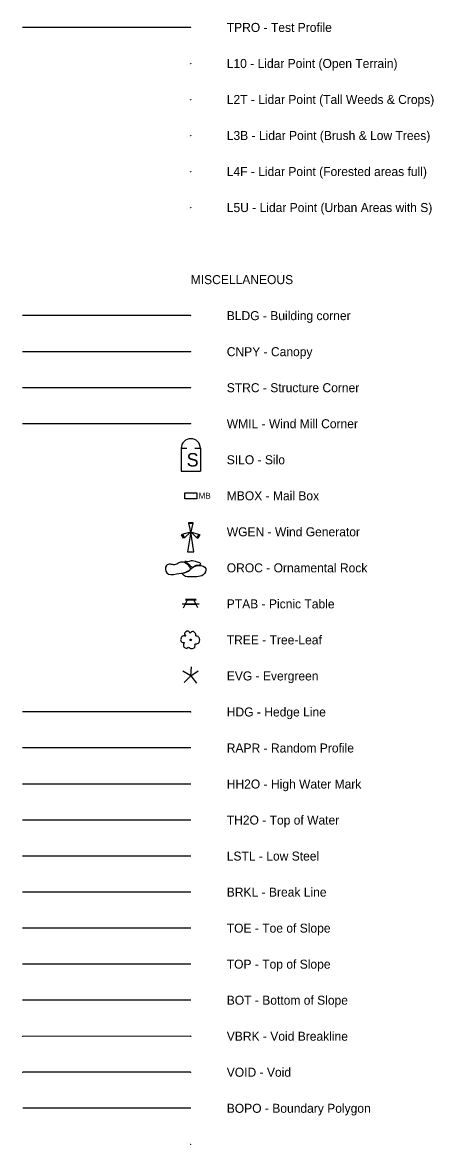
# Model space of a CAD drawing. Extents: x 2147712 to 2176316, y 2125036 to 2131746.
# Drawn here: x 2175974 to 2176316, y 2127274 to 2128208 of the extents above; entities that cross this region are included whole.
import ezdxf

# ---------------------------------------------------------------- set-up
doc = ezdxf.new("R2010")
doc.units = 0
for name, color, linetype in [('BLDG INP', 7, 'Continuous'), ('BRKLN', 7, 'Continuous'), ('Default', 7, 'Continuous'), ('HYD INP', 7, 'Continuous'), ('MANMD STRU INP', 7, 'Continuous'), ('PHO CTRL', 7, 'Continuous'), ('SPOT', 7, 'Continuous'), ('VEG INP', 7, 'Continuous'), ('VOID', 7, 'Continuous')]:
    doc.layers.add(name, color=color, linetype=linetype)

msp = doc.modelspace()

# ---------------------------------------------------------------- linework, layer by layer
at = {"layer": 'BLDG INP'}
for p, q in [((2176114.25, 2127963.72), (2175974.25, 2127963.72)), ((2176114.15, 2127963.52), (2176114.35, 2127963.92)), ((2176114.15, 2127963.92), (2176114.35, 2127963.52))]:
    msp.add_line(p, q, dxfattribs=at)
at = {"layer": 'BRKLN'}
for p, q in [((2176114.25, 2127603.72), (2175974.25, 2127603.72)), ((2176114.25, 2127483.72), (2175974.25, 2127483.72)), ((2176114.25, 2127453.72), (2175974.25, 2127453.72)), ((2176114.25, 2127423.72), (2175974.25, 2127423.72)), ((2176114.25, 2127393.72), (2175974.25, 2127393.72)), ((2176114.25, 2127303.72), (2175974.55, 2127303.72))]:
    msp.add_line(p, q, dxfattribs=at)
at = {"layer": 'Default'}
for p, q in [((2176114.25, 2127573.72), (2175974.25, 2127573.72)), ((2176114.25, 2127513.72), (2175974.25, 2127513.72))]:
    msp.add_line(p, q, dxfattribs=at)
at = {"layer": 'HYD INP'}
msp.add_line((2176114.25, 2127543.72), (2175974.25, 2127543.72), dxfattribs=at)
at = {"layer": 'MANMD STRU INP'}
for p, q in [((2176114.25, 2127933.72), (2175974.25, 2127933.72)), ((2176114.15, 2127933.52), (2176114.35, 2127933.92)), ((2176114.15, 2127933.92), (2176114.35, 2127933.52)), ((2176114.25, 2127903.72), (2175974.25, 2127903.72)), ((2176114.15, 2127903.52), (2176114.35, 2127903.92)), ((2176114.15, 2127903.92), (2176114.35, 2127903.52)), ((2176114.25, 2127873.72), (2175974.25, 2127873.72)), ((2176114.15, 2127873.52), (2176114.35, 2127873.92)), ((2176114.15, 2127873.92), (2176114.35, 2127873.52)), ((2176106.35, 2127853.32), (2176106.35, 2127834.12)), ((2176106.35, 2127853.32), (2176110.95, 2127853.32)), ((2176117.55, 2127853.32), (2176122.35, 2127853.32)), ((2176122.35, 2127853.32), (2176122.35, 2127834.12)), ((2176114.35, 2127843.72), (2176114.35, 2127843.72)), ((2176106.35, 2127834.12), (2176122.35, 2127834.12)), ((2176116.55, 2127815.32), (2176116.55, 2127815.32)), ((2176108.15, 2127720.32), (2176111.75, 2127727.52)), ((2176109.85, 2127727.52), (2176118.65, 2127727.52)), ((2176109.85, 2127727.22), (2176118.65, 2127727.22)), ((2176120.25, 2127720.32), (2176116.65, 2127727.52)), ((2176107.15, 2127723.72), (2176121.25, 2127723.72)), ((2176109.85, 2127723.52), (2176118.65, 2127723.52))]:
    msp.add_line(p, q, dxfattribs=at)
for points in [[(2176109.25, 2127816.32), (2176119.25, 2127816.32), (2176119.25, 2127811.12), (2176109.25, 2127811.12)], [(2176112.65, 2127791.62), (2176116.05, 2127791.62), (2176116.05, 2127790.82), (2176112.65, 2127790.82)], [(2176114.25, 2127783.72), (2176112.65, 2127790.82), (2176116.05, 2127790.82)], [(2176108.25, 2127778.32), (2176106.45, 2127781.32), (2176107.25, 2127781.82), (2176109.05, 2127778.82)], [(2176114.25, 2127783.72), (2176109.05, 2127778.82), (2176107.25, 2127781.82)], [(2176114.25, 2127783.72), (2176111.65, 2127767.02), (2176116.85, 2127767.02)], [(2176114.25, 2127783.72), (2176121.15, 2127781.62), (2176119.45, 2127778.62)], [(2176121.85, 2127781.22), (2176120.25, 2127778.22), (2176119.45, 2127778.62), (2176121.15, 2127781.62)]]:
    msp.add_lwpolyline(points, close=True, dxfattribs=at)
msp.add_arc((2176114.31, 2127853.29), 8, 0, 180, dxfattribs=at)
for points in [[(2176104.35, 2127757.92), (2176100.75, 2127756.32), (2176097.35, 2127756.72), (2176094.05, 2127755.72), (2176094.35, 2127749.52), (2176102.35, 2127748.62), (2176113.95, 2127753.12), (2176109.15, 2127758.12), (2176105.85, 2127758.42), (2176104.25, 2127757.82)], [(2176107.55, 2127749.22), (2176112.85, 2127751.62), (2176115.85, 2127754.02), (2176120.95, 2127755.72), (2176126.75, 2127753.22), (2176124.65, 2127747.92), (2176119.35, 2127746.32), (2176112.35, 2127746.22), (2176108.15, 2127747.62), (2176107.35, 2127749.02)], [(2176109.55, 2127758.62), (2176113.25, 2127756.32), (2176115.15, 2127754.42), (2176115.75, 2127754.32), (2176117.75, 2127755.52), (2176119.75, 2127755.92), (2176121.45, 2127756.22), (2176122.55, 2127757.02), (2176119.75, 2127758.42), (2176114.75, 2127759.52), (2176110.55, 2127758.92), (2176109.35, 2127759.02), (2176109.45, 2127758.72), (2176109.75, 2127758.42)]]:
    msp.add_spline(points, degree=3, dxfattribs=at)
at = {"layer": 'PHO CTRL'}
for p, q in [((2176114.25, 2128203.72), (2175974.25, 2128203.72)), ((2176114.15, 2128203.52), (2176114.35, 2128203.92)), ((2176114.15, 2128203.92), (2176114.35, 2128203.52)), ((2176114.15, 2128173.52), (2176114.35, 2128173.92)), ((2176114.15, 2128173.92), (2176114.35, 2128173.52)), ((2176114.15, 2128143.52), (2176114.35, 2128143.92)), ((2176114.15, 2128143.92), (2176114.35, 2128143.52)), ((2176114.15, 2128113.52), (2176114.35, 2128113.92)), ((2176114.15, 2128113.92), (2176114.35, 2128113.52)), ((2176114.15, 2128083.52), (2176114.35, 2128083.92)), ((2176114.15, 2128083.92), (2176114.35, 2128083.52)), ((2176114.15, 2128053.52), (2176114.35, 2128053.92)), ((2176114.15, 2128053.92), (2176114.35, 2128053.52))]:
    msp.add_line(p, q, dxfattribs=at)
at = {"layer": 'SPOT'}
for p, q in [((2176114.15, 2127273.52), (2176114.35, 2127273.92)), ((2176114.15, 2127273.92), (2176114.35, 2127273.52))]:
    msp.add_line(p, q, dxfattribs=at)
at = {"layer": 'VEG INP'}
for p, q in [((2176114.25, 2127663.72), (2176114.85, 2127671.22)), ((2176114.25, 2127663.72), (2176120.55, 2127667.92)), ((2176114.25, 2127663.72), (2176107.65, 2127667.62)), ((2176114.25, 2127663.72), (2176108.85, 2127658.32)), ((2176114.25, 2127663.72), (2176119.05, 2127657.72)), ((2176114.25, 2127633.72), (2175974.25, 2127633.72)), ((2176114.15, 2127633.52), (2176114.35, 2127633.92)), ((2176114.15, 2127633.92), (2176114.35, 2127633.52))]:
    msp.add_line(p, q, dxfattribs=at)
msp.add_circle((2176114.25, 2127693.72), 0.703, dxfattribs=at)
msp.add_spline([(2176113.65, 2127699.42), (2176114.85, 2127700.32), (2176116.65, 2127700.62), (2176117.55, 2127699.72), (2176118.45, 2127698.52), (2176118.45, 2127697.02), (2176119.65, 2127696.72), (2176120.85, 2127696.12), (2176121.45, 2127694.92), (2176121.75, 2127693.72), (2176121.15, 2127691.62), (2176119.95, 2127690.72), (2176118.75, 2127690.42), (2176117.85, 2127690.42), (2176117.85, 2127688.92), (2176117.55, 2127687.72), (2176116.65, 2127686.82), (2176114.85, 2127686.52), (2176113.65, 2127686.82), (2176112.45, 2127687.72), (2176110.95, 2127686.82), (2176109.75, 2127687.12), (2176108.55, 2127688.02), (2176108.25, 2127689.22), (2176108.25, 2127690.42), (2176109.15, 2127691.32), (2176107.65, 2127691.62), (2176106.15, 2127692.52), (2176105.85, 2127693.72), (2176106.15, 2127695.22), (2176106.45, 2127696.12), (2176107.35, 2127696.72), (2176108.25, 2127697.02), (2176109.15, 2127697.02), (2176110.05, 2127696.72), (2176109.45, 2127697.92), (2176109.15, 2127699.12), (2176109.75, 2127700.02), (2176110.95, 2127700.92), (2176112.15, 2127700.92), (2176113.05, 2127700.32), (2176113.35, 2127700.02), (2176113.65, 2127699.42)], degree=3, dxfattribs=at)
at = {"layer": 'VOID'}
for p, q in [((2175974.15, 2127363.52), (2175974.35, 2127363.92)), ((2175974.15, 2127363.92), (2175974.35, 2127363.52)), ((2176114.25, 2127363.72), (2175974.35, 2127363.52)), ((2176114.15, 2127363.52), (2176114.35, 2127363.92)), ((2176114.15, 2127363.92), (2176114.35, 2127363.52)), ((2175974.25, 2127333.52), (2175974.45, 2127333.92)), ((2175974.25, 2127333.92), (2175974.45, 2127333.52)), ((2176114.15, 2127333.92), (2175974.45, 2127333.92)), ((2176114.15, 2127333.52), (2176114.35, 2127333.92)), ((2176114.15, 2127333.92), (2176114.35, 2127333.52))]:
    msp.add_line(p, q, dxfattribs=at)

# ---------------------------------------------------------------- texts
at = {"layer": 'Default'}
for s, p in [('TPRO - Test Profile', (2176144.25, 2128199.97)), ('L10 - Lidar Point (Open Terrain)', (2176144.25, 2128169.97)), ('L2T - Lidar Point (Tall Weeds & Crops)', (2176144.25, 2128139.97)), ('L3B - Lidar Point (Brush & Low Trees)', (2176144.25, 2128109.97)), ('L4F - Lidar Point (Forested areas full)', (2176144.25, 2128079.97)), ('L5U - Lidar Point (Urban Areas with S)', (2176144.25, 2128049.97)), ('MISCELLANEOUS', (2176114.25, 2127989.97)), ('BLDG - Building corner', (2176144.25, 2127959.97)), ('CNPY - Canopy', (2176144.25, 2127929.97)), ('STRC - Structure Corner', (2176144.25, 2127899.97)), ('WMIL - Wind Mill Corner', (2176144.25, 2127869.97)), ('SILO - Silo', (2176144.25, 2127839.97)), ('MBOX - Mail Box', (2176144.25, 2127809.97)), ('WGEN - Wind Generator', (2176144.25, 2127779.97)), ('OROC - Ornamental Rock', (2176144.25, 2127749.97)), ('PTAB - Picnic Table', (2176144.25, 2127719.97)), ('TREE - Tree-Leaf', (2176144.25, 2127689.97)), ('EVG - Evergreen', (2176144.25, 2127659.97)), ('HDG - Hedge Line', (2176144.25, 2127629.97)), ('RAPR - Random Profile', (2176144.25, 2127599.97)), ('HH2O - High Water Mark', (2176144.25, 2127569.97)), ('TH2O - Top of Water', (2176144.25, 2127539.97)), ('LSTL - Low Steel', (2176144.25, 2127509.97)), ('BRKL - Break Line', (2176144.25, 2127479.97)), ('TOE - Toe of Slope', (2176144.25, 2127449.97)), ('TOP - Top of Slope', (2176144.25, 2127419.97)), ('BOT - Bottom of Slope', (2176144.25, 2127389.97)), ('VBRK - Void Breakline', (2176144.25, 2127359.97)), ('VOID - Void', (2176144.25, 2127329.97)), ('BOPO - Boundary Polygon', (2176144.25, 2127299.97))]:
    msp.add_text(s, height=7.5, dxfattribs=at).set_placement(p)
at = {"layer": 'MANMD STRU INP'}
for s, height, p in [('S', 11.2, (2176110.85, 2127838.12)), ('MB', 5, (2176120.85, 2127811.22))]:
    msp.add_text(s, height=height, dxfattribs=at).set_placement(p)

doc.saveas('drawing.dxf')
